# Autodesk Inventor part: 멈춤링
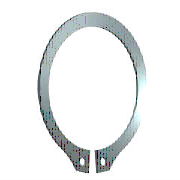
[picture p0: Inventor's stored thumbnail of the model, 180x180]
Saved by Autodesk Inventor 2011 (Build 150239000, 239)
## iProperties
Created: 2014-12
Part Number: 멈춤링
Material: 강, 연강
Description: 리테이닝 링(C형)
Document SubType Name: Modeling
Standard: KS B 1336
Designer: KYOUNG IL JANG
Standards Organization: KS
Language: ko-KR
Size Designation: 17 x 1
Categories: <MemberInstance><Categories><Category DisplayName="샤프트 부품" InternalName="7f7aeb1f-a693-4053-b835-cee3144e0d98" Mnemonic="SHFT"><Category DisplayName="써클립" Inter
Density: 7.86 g/cm^3
Mass: 0.979804 g
Surface Area: 3.83537 cm^2
Volume: 0.124657 cm^3
Company: 한국ATC센터
Author: KYOUNG IL JANG
IsCustomPart: 0
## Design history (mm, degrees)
sketch "스케치1"
  geometry: L1 (-6, 0)-(6, 0) reference; L2 (0, 20.189)-(0, -80.536) reference; L3 (-48.09, 0)-(48.09, 0) reference; L4 (-0.425, -16.589)-(-0.425, -20.289); L5 (-0.425, -6.54)-(-0.425, -13.29); L6 (-2.795, 2.2)-(3.672, 2.2); L7 (0.425, -6.54)-(0.425, -13.29); L8 (0.425, -16.589)-(0.425, -20.289); C1 r 0.85 at (-1.7, -18.452); C2 r 0.85 at (1.7, -18.452); A1 r 8.1 centre (0, -8.5) between (0.425, -16.589) and (-0.425, -16.589); A2 r 10.15 centre (0, -7.95) between (4.363, -17.114) and (-4.363, -17.114); A3 r 11.797 centre (0, -8.5) between (-1.986, -20.128) and (-0.425, -20.289); A4 r 1.7 centre (-1.7, -18.452) between (-3.397, -18.551) and (-1.986, -20.128); A5 r 1.7 centre (-5.094, -18.649) between (-3.397, -18.551) and (-4.363, -17.114); A6 r 1.7 centre (5.094, -18.649) between (4.363, -17.114) and (3.397, -18.551); A7 r 1.7 centre (1.7, -18.452) between (1.986, -20.128) and (3.397, -18.551); A8 r 11.797 centre (0, -8.5) between (0.425, -20.289) and (1.986, -20.128)
  constraints: 16 point on circle, 12 end point, 10 centre point, 9 symmetric about line, 5 point on line, 4 tangent, 3 coincident, 2 horizontal, 1 perpendicular, 1 vertical, 5 other
  dimensions: "d0" = 16.2 diameter of A1 (= ND); "d1" = 3.7 distance of L4.end L4.start (= SRB2); "d6" = 0.425 distance between parallel lines of L2 L5 (= 0.25 x SD5); "d7" = 2.2 distance between parallel lines of L6 L3 (= SRB1); "d8" = 0.55 distance of A1.centre A2.centre (= 0.25 x SRB1); "d9" = 1.7 radius of A4 (= SD5); "d10" = 1.7 radius of A5 (= SD5); "d11" = 1.275 distance from line of L4 A4.centre (= 0.75 x SD5); "d12" = 1.7 diameter of C1 (= SD5); "d13" = 1.7 diameter of C2 (= SD5); "d14" = 8.5 distance from line of A1.centre L1 (= 0.5 x WD)
extrude "본체" new body sketch "스케치1" distance "d2" = 1 (= SD); taper "d3" = 0 deg
workaxis "Work Axis1"
workplane "Work Plane1"
body "Solid1"
other parameters: "WD" = 17 (= WDMIN) [user parameter; used in 1 equation term], "SD" = 1 [user parameter; used in 1 equation term], "SRB1" = 2.2 [user parameter; used in 2 equation terms], "ND" = 16.2 [user parameter; used in 1 equation term], "SRB2" = 3.7 [user parameter; used in 1 equation term], "SD5" = 1.7 [user parameter; used in 6 equation terms], "d15" = 0, "d16" = 0, "d17" = 0, "d41" = 0, "d42" = 0, "WDMIN" = 17 [user parameter; used in 1 equation term], "SD3" = 15.7 [user parameter], "WDMAX" = 18 [user parameter]
